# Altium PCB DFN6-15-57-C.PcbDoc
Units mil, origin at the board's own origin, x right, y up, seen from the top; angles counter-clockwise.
Board outline 600 x 1500 mil, 4 copper layers (Top Layer, Metal 2, Metal 3, Bottom Layer), stack 61.6 mil thick; 6 components, 4 nets, 39 pads, 257 vias.
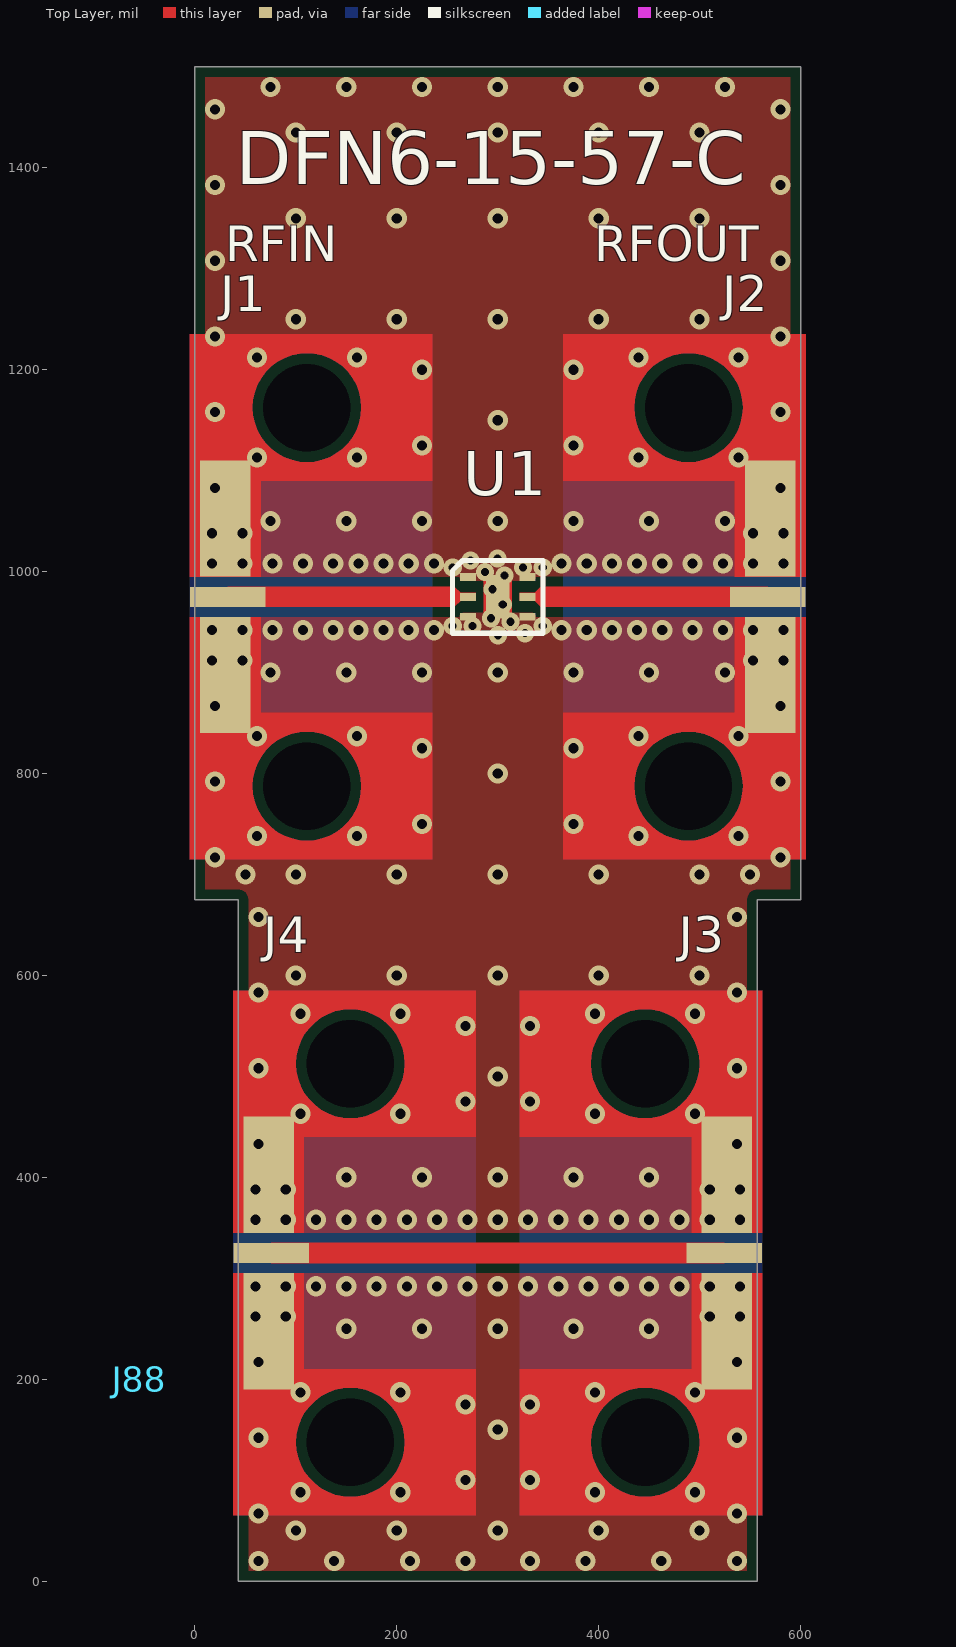
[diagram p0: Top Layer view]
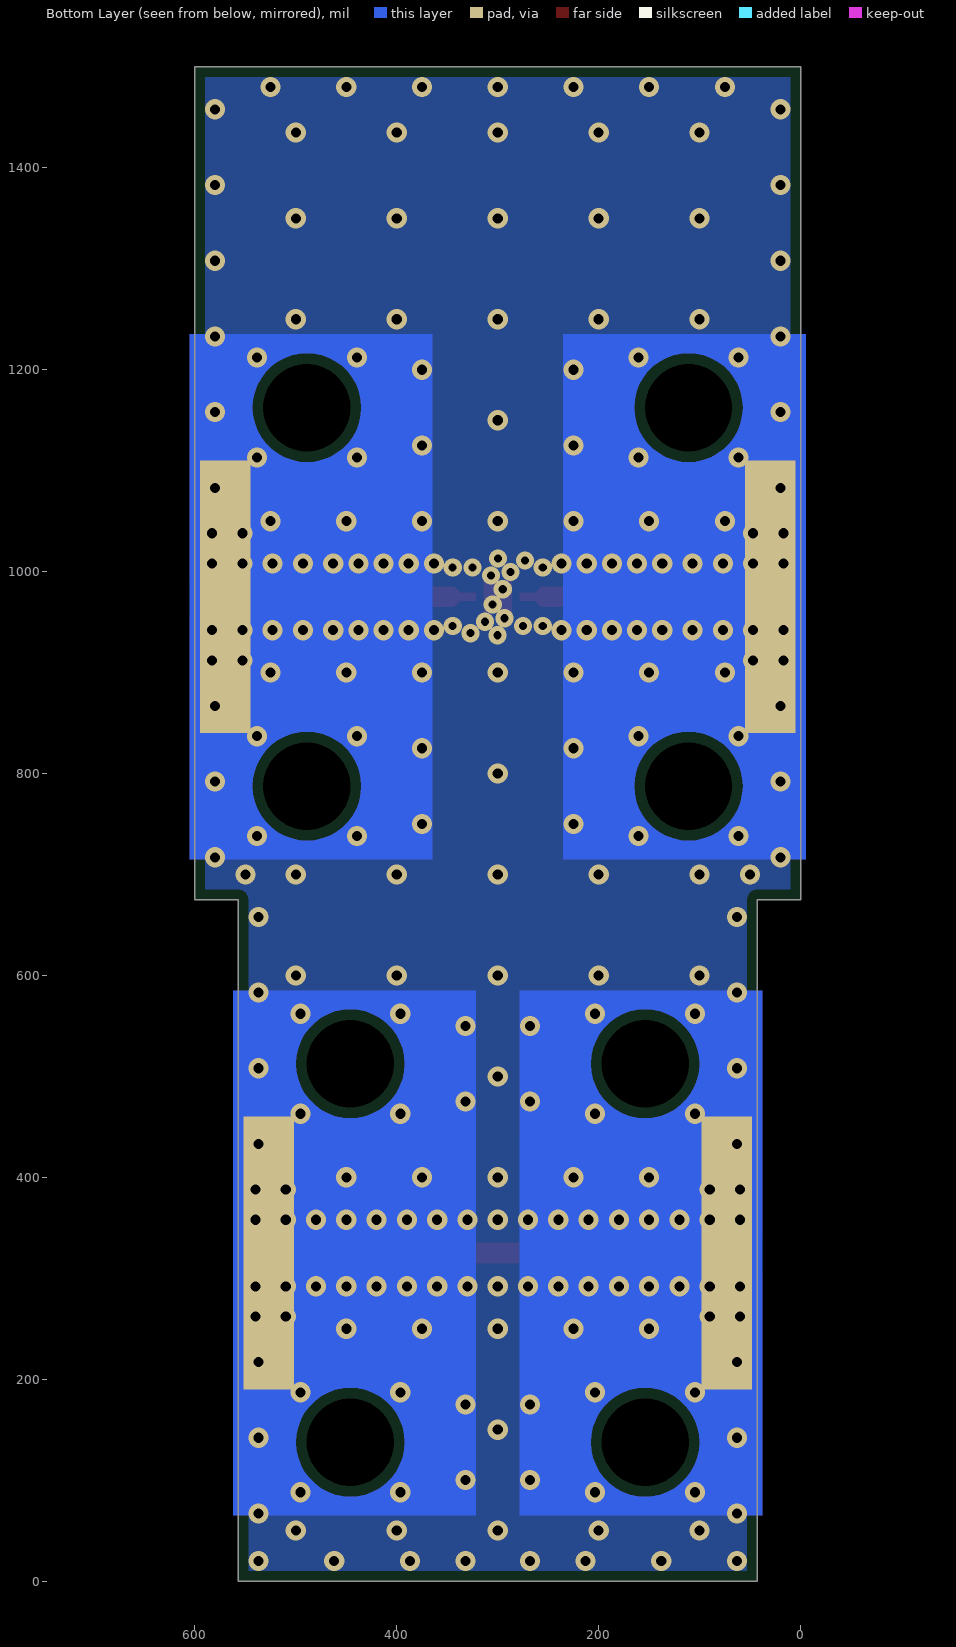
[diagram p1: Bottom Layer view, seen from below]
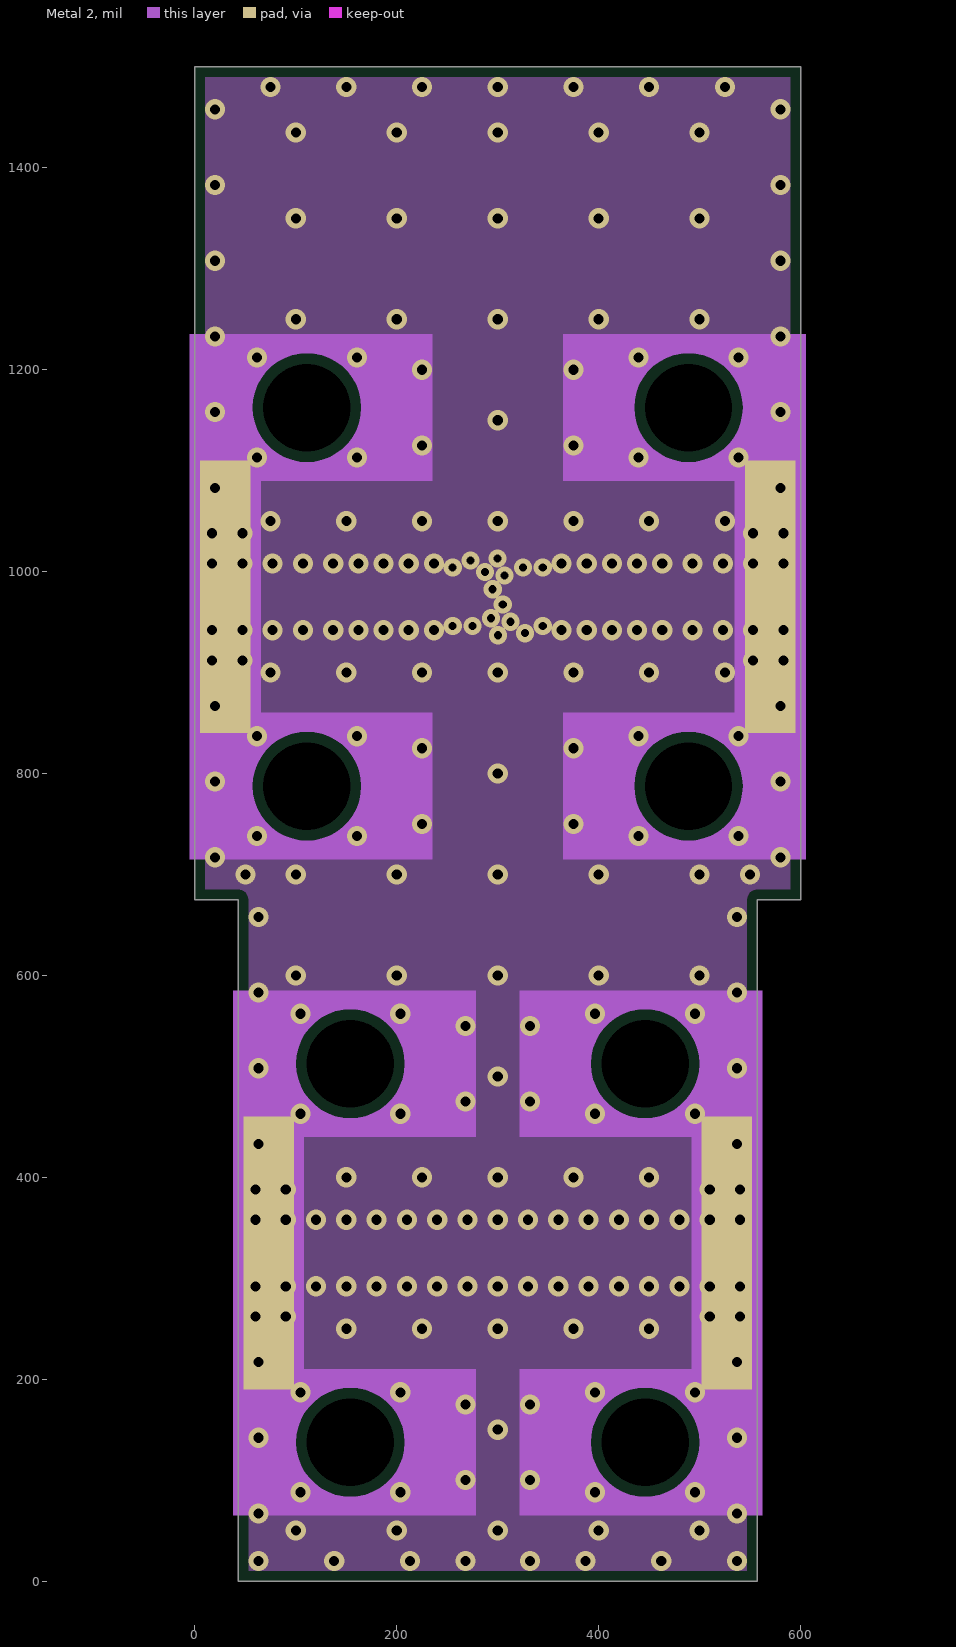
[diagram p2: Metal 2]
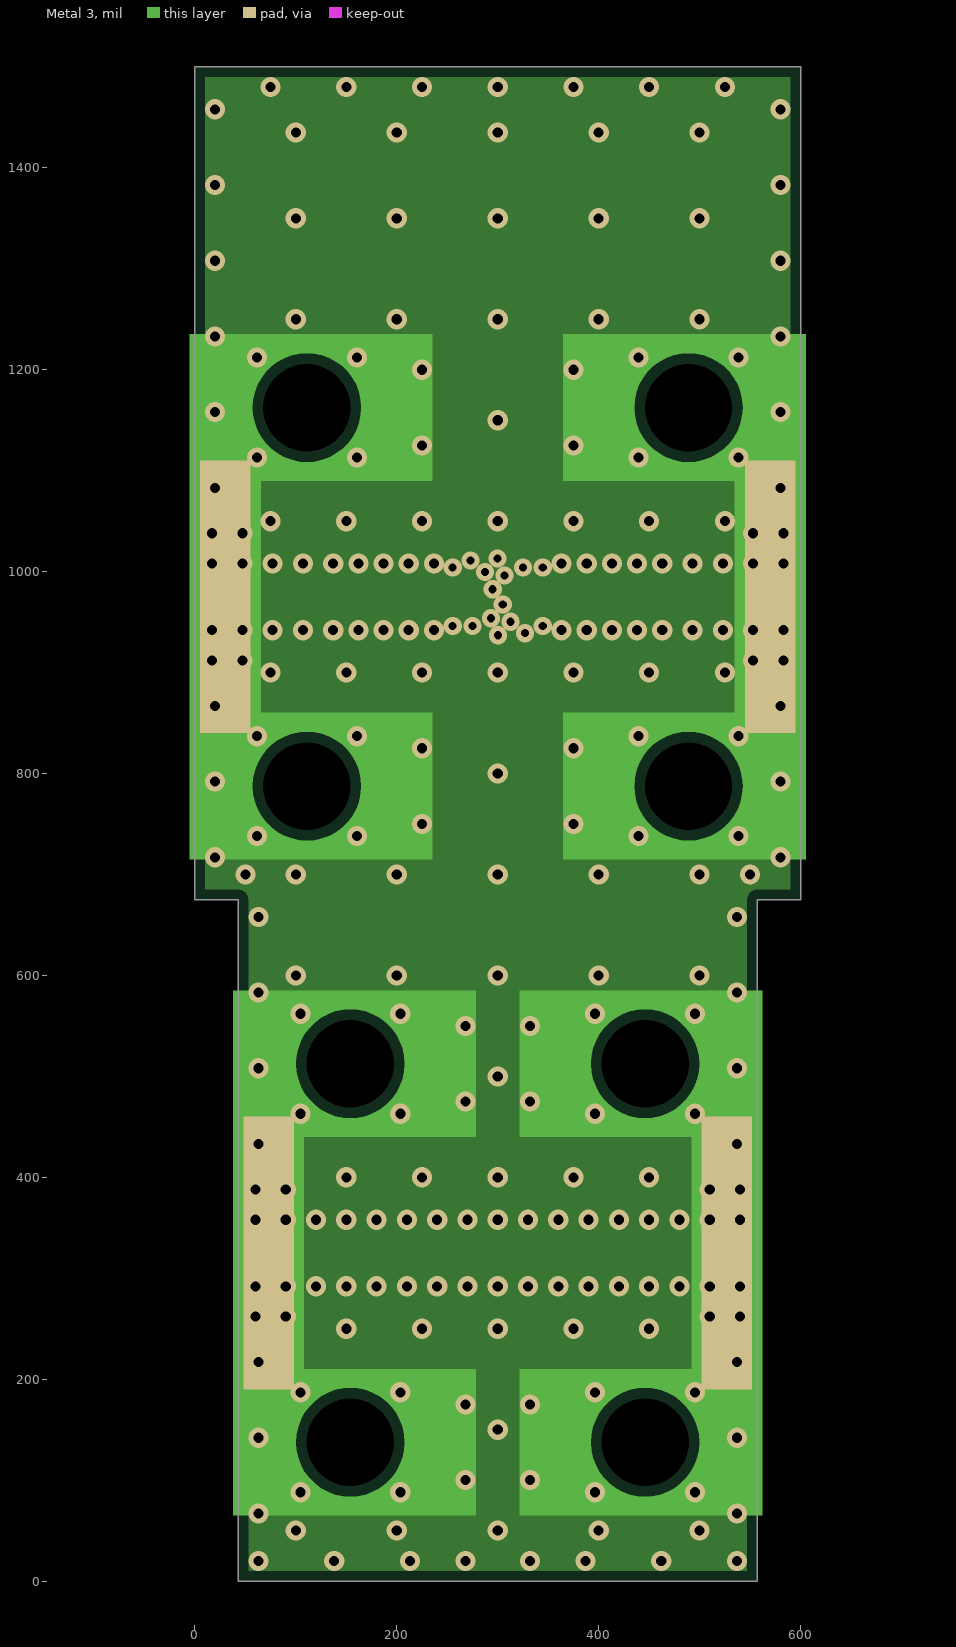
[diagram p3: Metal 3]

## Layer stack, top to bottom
Top Solder: solder mask 0.4, Solder Resist, Dk 4.1
Top Layer: signal copper 1.4
Dielectric 2: core 12, RO4003C, Dk 3.38
Metal 2: signal copper 1.4
Dielectric 1: prepreg 32, FR-4, Dk 4.8
Metal 3: signal copper 1.4
Dielectric 3: core 12, RO4003C, Dk 3.38
Bottom Layer: signal copper 1.4
Bottom Solder: solder mask 0.4, Solder Resist, Dk 4.1

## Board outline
0,675 0,1500 600,1500 600,675 557,675 557,0 43,0 43,675

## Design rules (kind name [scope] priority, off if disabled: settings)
BackDrilling [IsVia and not InNet('GND')] p1: maxstublength=5 usetopbackdrill=TRUE usebottombackdrill=TRUE holeoversize=10 holetolplus=0.2 holetolminus=0.2
BoardOutlineClearance BoardOutlineClearance_Solder_Mask [OnLayer('Top Solder') Or OnLayer('Bottom Solder')] p1: gap=0 ignorepadtopadclearanceinfootprint=FALSE
BoardOutlineClearance [All] p2: gap=10 ignorepadtopadclearanceinfootprint=FALSE
Clearance Clearance_I/O [InNetClass('I/O') vs InNet('GND')] p1: gap=7 ignorepadtopadclearanceinfootprint=TRUE
Clearance Clearance_RF_Strip [InNetClass('RF_Strip') vs InNet('GND')] p2: gap=40 ignorepadtopadclearanceinfootprint=TRUE
Clearance Clearance_RF_15-15-8 [InNetClass('RF_15-15-8') vs InNet('GND')] p3: gap=15 ignorepadtopadclearanceinfootprint=TRUE
Clearance Clearance_RF_20-10-12 [InNetClass('RF_20-10-12') vs InNet('GND')] p4: gap=10 ignorepadtopadclearanceinfootprint=TRUE
Clearance Clearance_RF_30-20-16 [InNetClass('RF_30-20-16') vs InNet('GND')] p5: gap=20 ignorepadtopadclearanceinfootprint=TRUE
Clearance Clearance_RF_28-21-16_FR4 [InNetClass('RF_28-21-16_FR4') vs InNet('GND')] p6: gap=21 ignorepadtopadclearanceinfootprint=TRUE
Clearance Clearance_RF_15-27p5-8 [InNetClass('RF_15-27p5-8') vs InNet('GND')] p7: gap=27.5 ignorepadtopadclearanceinfootprint=TRUE
Clearance Clearance_RF_25-22-40_75ohm [InNetClass('RF_25-22-40_75ohm') vs InNet('GND')] p8: gap=22 ignorepadtopadclearanceinfootprint=TRUE
Clearance Clearance_GND [InNet('GND')] p9: gap=10 ignorepadtopadclearanceinfootprint=TRUE
Clearance [All] p10: gap=6 ignorepadtopadclearanceinfootprint=TRUE
ComponentClearance ComponentClearance_Heatsink [InComponent('All') And OnLayer('Top Layer') vs HasFootprint('Heatsink_wFid')] p1: gap=0 collisioncheckmode=3 verticalgap=0 showdistances=FALSE
ComponentClearance ComponentClearance_PCB_Frame [InComponent('All') And OnLayer('Top Layer') vs HasFootprint('PCB_Frame')] p2: gap=0 collisioncheckmode=3 verticalgap=0 showdistances=FALSE
ComponentClearance [All] p3: gap=10 collisioncheckmode=3 verticalgap=10 showdistances=TRUE
HoleSize [All] p1: absolutevalues=TRUE maxlimit=200 minlimit=8 maxpercent=80.000 minpercent=20.000
MinimumSolderMaskSliver [All] p1: minsoldermaskwidth=5
PlaneClearance [Not InNet('GND')] p1: clearance=20
PlaneConnect [InNet('GND')] p1: planeconnectstyle=Direct reliefexpansion=20 reliefentries=4 reliefconductorwidth=10 reliefairgap=10
PolygonConnect [All vs InNet('GND')] p1: connectstyle=Direct reliefconductorwidth=10 reliefentries=4 polygonreliefangle="90 Angle" airgapwidth=10
RoutingVias [All] p1: holewidth=10 width=20 viastyle="Through Hole" minholewidth=8 minwidth=18 maxholewidth=23.62 maxwidth=33.62
SilkToSilkClearance [All] p1: silktosilkclearance=5
SilkToSolderMaskClearance [IsPad] p1: minsilkscreentomaskgap=5 clearancetoexposedcopper=TRUE
SolderMaskExpansion [All] p1: expansion=1 istentingtop=FALSE
UnRoutedNet [All] p1: checkbadconnections=TRUE
Width [All] p1: maxlimit=100 minlimit=6 preferedwidth=10
22 further rules are at their usual default settings.

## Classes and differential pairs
component class DFN6-15-57-C: J1 J2 J3 J4 U1
net class RF_20-10-12: NetJ1_1 NetJ2_1

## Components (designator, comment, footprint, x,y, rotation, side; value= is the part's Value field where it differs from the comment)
J1 "Clamp_27G_Southwest_RevC" Clamp_27G_Southwest_RevC 0,975 r0 top
J2 "Clamp_27G_Southwest_RevC" Clamp_27G_Southwest_RevC 600,975 r180 top (schematic designator J3)
J3 "Clamp_27G_Southwest_RevC" Clamp_27G_Southwest_RevC 557,325 r180 top (schematic designator J4)
J4 "Clamp_27G_Southwest_RevC" Clamp_27G_Southwest_RevC 43,325 r0 top (schematic designator J5)
J88 "Comment" PCB_Fab_20T-10G-12D_4003 -55,200 r0 top locked
U1 "DFN6_1.5x1.5mm_RevG" DFN6_1.5x1.5mm_RevG 300,975 r0 top

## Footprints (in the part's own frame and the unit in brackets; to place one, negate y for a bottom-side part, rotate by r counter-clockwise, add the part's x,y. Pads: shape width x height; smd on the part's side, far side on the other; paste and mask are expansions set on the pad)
Clamp_27G_Southwest_RevC [mil] "292-04A-6  for CPWG"
  rect 75x20 smd paste-30: 1(32.5,0)
  rect 50x115 smd paste-30 mask-300: 2(30,-77.5) 2(30,77.5)
  rect 50x270 on Mid1: 2(30,0)
  rect 50x270 smd far side: 2(30,0)
  rect 50x270 on Mid2: 2(30,0)
  round 0 hole 86.61 unplated: 3(111,-187.5) 3(111,187.5)
  Top Layer region: -5,20 -5,260 235,260 235,187.5 165,187.5 160.89,208.16 149.18,225.68 131.66,237.39 111,241.5 111,241.5 90.34,237.39 72.82,225.68 61.11,208.16 57,187.5 57,187.5 61.11,166.84 72.82,149.32 90.34,137.61 111,133.5 111,133.5 131.66,137.61 149.18,149.32 160.89,166.84 165,187.5 165,187.5 235,187.5 235,115 65,115 65,20
  Top Layer region: -5,-20 -5,-260 235,-260 235,-187.5 165,-187.5 160.89,-208.16 149.18,-225.68 131.66,-237.39 111,-241.5 111,-241.5 90.34,-237.39 72.82,-225.68 61.11,-208.16 57,-187.5 57,-187.5 61.11,-166.84 72.82,-149.32 90.34,-137.61 111,-133.5 111,-133.5 131.66,-137.61 149.18,-149.32 160.89,-166.84 165,-187.5 165,-187.5 235,-187.5 235,-115 65,-115 65,-20
  Top Layer pour cut-out: 57,187.5 61.11,208.16 72.82,225.68 90.34,237.39 111,241.5 111,241.5 131.66,237.39 149.18,225.68 160.89,208.16 165,187.5 165,187.5 160.89,166.84 149.18,149.32 131.66,137.61 111,133.5 111,133.5 90.34,137.61 72.82,149.32 61.11,166.84 57,187.5
  Top Layer pour cut-out: 57,-187.5 61.11,-166.84 72.82,-149.32 90.34,-137.61 111,-133.5 111,-133.5 131.66,-137.61 149.18,-149.32 160.89,-166.84 165,-187.5 165,-187.5 160.89,-208.16 149.18,-225.68 131.66,-237.39 111,-241.5 111,-241.5 90.34,-237.39 72.82,-225.68 61.11,-208.16 57,-187.5
  Metal 2 region: -5,260 235,260 235,187.5 165,187.5 160.89,208.16 149.18,225.68 131.66,237.39 111,241.5 111,241.5 90.34,237.39 72.82,225.68 61.11,208.16 57,187.5 57,187.5 61.11,166.84 72.82,149.32 90.34,137.61 111,133.5 111,133.5 131.66,137.61 149.18,149.32 160.89,166.84 165,187.5 165,187.5 235,187.5 235,115 65,115 65,-115 235,-115 235,-187.5 165,-187.5 160.89,-166.84 149.18,-149.32 131.66,-137.61 111,-133.5 111,-133.5 90.34,-137.61 72.82,-149.32 61.11,-166.84 57,-187.5 57,-187.5 61.11,-208.16 72.82,-225.68 90.34,-237.39 111,-241.5 111,-241.5 131.66,-237.39 149.18,-225.68 160.89,-208.16 165,-187.5 165,-187.5 235,-187.5 235,-260 -5,-260
  Metal 2 pour cut-out: 57,187.5 61.11,208.16 72.82,225.68 90.34,237.39 111,241.5 111,241.5 131.66,237.39 149.18,225.68 160.89,208.16 165,187.5 165,187.5 160.89,166.84 149.18,149.32 131.66,137.61 111,133.5 111,133.5 90.34,137.61 72.82,149.32 61.11,166.84 57,187.5
  Metal 2 pour cut-out: 57,-187.5 61.11,-166.84 72.82,-149.32 90.34,-137.61 111,-133.5 111,-133.5 131.66,-137.61 149.18,-149.32 160.89,-166.84 165,-187.5 165,-187.5 160.89,-208.16 149.18,-225.68 131.66,-237.39 111,-241.5 111,-241.5 90.34,-237.39 72.82,-225.68 61.11,-208.16 57,-187.5
  Metal 3 region: -5,260 235,260 235,187.5 165,187.5 160.89,208.16 149.18,225.68 131.66,237.39 111,241.5 111,241.5 90.34,237.39 72.82,225.68 61.11,208.16 57,187.5 57,187.5 61.11,166.84 72.82,149.32 90.34,137.61 111,133.5 111,133.5 131.66,137.61 149.18,149.32 160.89,166.84 165,187.5 165,187.5 235,187.5 235,115 65,115 65,-115 235,-115 235,-187.5 165,-187.5 160.89,-166.84 149.18,-149.32 131.66,-137.61 111,-133.5 111,-133.5 90.34,-137.61 72.82,-149.32 61.11,-166.84 57,-187.5 57,-187.5 61.11,-208.16 72.82,-225.68 90.34,-237.39 111,-241.5 111,-241.5 131.66,-237.39 149.18,-225.68 160.89,-208.16 165,-187.5 165,-187.5 235,-187.5 235,-260 -5,-260
  Metal 3 pour cut-out: 57,187.5 61.11,208.16 72.82,225.68 90.34,237.39 111,241.5 111,241.5 131.66,237.39 149.18,225.68 160.89,208.16 165,187.5 165,187.5 160.89,166.84 149.18,149.32 131.66,137.61 111,133.5 111,133.5 90.34,137.61 72.82,149.32 61.11,166.84 57,187.5
  Metal 3 pour cut-out: 57,-187.5 61.11,-166.84 72.82,-149.32 90.34,-137.61 111,-133.5 111,-133.5 131.66,-137.61 149.18,-149.32 160.89,-166.84 165,-187.5 165,-187.5 160.89,-208.16 149.18,-225.68 131.66,-237.39 111,-241.5 111,-241.5 90.34,-237.39 72.82,-225.68 61.11,-208.16 57,-187.5
  Bottom Layer region: -5,260 235,260 235,187.5 165,187.5 160.89,208.16 149.18,225.68 131.66,237.39 111,241.5 111,241.5 90.34,237.39 72.82,225.68 61.11,208.16 57,187.5 57,187.5 61.11,166.84 72.82,149.32 90.34,137.61 111,133.5 111,133.5 131.66,137.61 149.18,149.32 160.89,166.84 165,187.5 165,187.5 235,187.5 235,-187.5 165,-187.5 160.89,-166.84 149.18,-149.32 131.66,-137.61 111,-133.5 111,-133.5 90.34,-137.61 72.82,-149.32 61.11,-166.84 57,-187.5 57,-187.5 61.11,-208.16 72.82,-225.68 90.34,-237.39 111,-241.5 111,-241.5 131.66,-237.39 149.18,-225.68 160.89,-208.16 165,-187.5 165,-187.5 235,-187.5 235,-260 -5,-260
  Bottom Layer pour cut-out: 57,187.5 61.11,208.16 72.82,225.68 90.34,237.39 111,241.5 111,241.5 131.66,237.39 149.18,225.68 160.89,208.16 165,187.5 165,187.5 160.89,166.84 149.18,149.32 131.66,137.61 111,133.5 111,133.5 90.34,137.61 72.82,149.32 61.11,166.84 57,187.5
  Bottom Layer pour cut-out: 57,-187.5 61.11,-166.84 72.82,-149.32 90.34,-137.61 111,-133.5 111,-133.5 131.66,-137.61 149.18,-149.32 160.89,-166.84 165,-187.5 165,-187.5 160.89,-208.16 149.18,-225.68 131.66,-237.39 111,-241.5 111,-241.5 90.34,-237.39 72.82,-225.68 61.11,-208.16 57,-187.5
DFN6_1.5x1.5mm_RevG [mm] "Standard Footprint"
  rect 0.4x0.2 smd paste-100: 1(-0.75,0.5) 2(-0.75,0) 3(-0.75,-0.5) 4(0.75,-0.5) 5(0.75,0) 6(0.75,0.5)
  rect 0.6x1.1 smd paste-100: 7(0,0)
  silkscreen extent -1.14,-0.92 1.14,0.92
PCB_Fab_20T-10G-12D_4003 [mil] "20mil RF 10mil Gap  12mil Dielectric"

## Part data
J1 J2 J3 J4: library part RF_Conn
U1: library part DFN6_1.5x1.5mm, "DFN6 1.5x1.5mm"

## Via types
v1: diameter 20/20/20/20 (per signal layer), hole 10, Top Layer to Bottom Layer, tented both sides, 233 vias
v2: diameter 18/18/18/18 (per signal layer), hole 8, Top Layer to Bottom Layer, tented both sides, 14 vias
v3: diameter 20/20/20/20 (per signal layer), hole 10, Top Layer to Bottom Layer, tented bottom, 8 vias
v4: diameter 18/18/18/18 (per signal layer), hole 8, Top Layer to Bottom Layer, tented bottom, 2 vias

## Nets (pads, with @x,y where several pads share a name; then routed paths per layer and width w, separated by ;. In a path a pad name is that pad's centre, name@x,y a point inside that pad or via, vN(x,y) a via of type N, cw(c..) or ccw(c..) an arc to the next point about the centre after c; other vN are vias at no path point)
GND: J1.2 J2.2 J3.2 J4.2 U1.1 U1.3 U1.4 U1.6 U1.7
  other v1: 63,20 138,20 213,20 268,20 332,20 387,20 462,20 537,20 100,50 200,50 300,50 400,50 500,50 104.5,88 203.5,88 396.5,88 495.5,88 268,100 332,100 63,142 537,142 300,150 268,175 332,175 104.5,187 203.5,187 396.5,187 495.5,187 63,217 537,217 150,250 225,250 300,250 375,250 450,250 60,262 90,262 510,262 540,262 60,292 90,292 120,292 150,292 180,292 210,292 240,292 270,292 300,292 330,292 360,292 390,292 420,292 450,292 480,292 510,292 540,292 60,358 90,358 120,358 150,358 180,358 210,358 240,358 270,358 300,358 330,358 360,358 390,358 420,358 450,358 480,358 510,358 540,358 60,388 90,388 510,388 540,388 150,400 225,400 300,400 375,400 450,400 63,433 537,433 104.5,463 203.5,463 396.5,463 495.5,463 268,475 332,475 300,500 63,508 537,508 268,550 332,550 104.5,562 203.5,562 396.5,562 495.5,562 100,600 200,600 300,600 400,600 500,600 63,658 537,658 50,700 100,700 200,700 300,700 400,700 500,700 550,700 61.5,738 160.5,738 439.5,738 538.5,738 225,750 375,750 20,792 580,792 300,800 225,825 375,825 61.5,837 160.5,837 439.5,837 538.5,837 20,867 580,867 75,900 150,900 225,900 300,900 375,900 450,900 525,900 17,912 47,912 553,912 583,912 17,942 47,942 77,942 107,942 137,942 161.93,942 186.86,942 211.79,942 236.72,942 363.28,942 388.21,942 413.14,942 438.07,942 463,942 493,942 523,942 553,942 583,942 17,1008 47,1008 77,1008 107,1008 137,1008 161.93,1008 186.86,1008 211.79,1008 236.72,1008 363.28,1008 388.21,1008 413.14,1008 438.07,1008 463,1008 493,1008 523,1008 553,1008 583,1008 17,1038 47,1038 553,1038 583,1038 75,1050 150,1050 225,1050 300,1050 375,1050 450,1050 525,1050 20,1083 580,1083 61.5,1113 160.5,1113 439.5,1113 538.5,1113 225,1125 375,1125 300,1150 20,1158 580,1158 225,1200 375,1200 61.5,1212 160.5,1212 439.5,1212 538.5,1212 100,1250 200,1250 300,1250 400,1250 500,1250 20,1308 580,1308 100,1350 200,1350 300,1350 400,1350 500,1350 20,1383 580,1383 100,1435 200,1435 300,1435 400,1435 500,1435 20,1458 580,1458 75,1480 150,1480 225,1480 300,1480 375,1480 450,1480 525,1480
  other v2: 300.2,937.01 327,939 255.37,946 275,946 344.63,946 312.65,950.36 305,967.43 295,982.57 287.35,999.64 255.37,1004 325,1004 344.63,1004 273,1011 299.8,1012.99
  other v3: 63,67 537,67 63,583 537,583 20,717 580,717 20,1233 580,1233
  other v4: 293.23,953.8 306.77,996.2
NetJ1_1: J1.1 U1.2
NetJ2_1: J2.1 U1.5
NetJ3_1: J3.1 J4.1
pads on no net: J1.3 J2.3 J3.3 J4.3

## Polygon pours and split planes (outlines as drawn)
GND on Top Layer "GND_L01_P000" (solid, pour order 0): 0,0 600,0 600,1500 0,1500
GND on Bottom Layer "GND_L04_P001" (solid, pour order 1): 0,0 600,0 600,1500 0,1500
GND on Metal 2 "NONET_L-01_P-001" (solid, pour order 2): 0,0 600,0 600,1500 0,1500
GND on Metal 3 "NONET_L-01_P-001" (solid, pour order 3): 0,0 600,0 600,1500 0,1500

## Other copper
Top Layer:
  rectangle net GND: 38,345 58,360
  rectangle net GND: 38,290 58,305
  rectangle net GND: -5,940 15,955
  rectangle net GND: -5,995 15,1010
  region net GND: 562,305 542,305 542,290 562,290
  region net GND: 562,360 542,360 542,345 562,345
  region net GND: 605,955 585,955 585,940 605,940
  region net GND: 605,1010 585,1010 585,995 605,995
  pour cut-out: 286,990.75 262.6,990.75 262.6,995 255,995 255,955 262.6,955 262.6,959.25 286,959.25
  pour cut-out: 314,990.75 337.4,990.75 337.4,995 345,995 345,955 337.4,955 337.4,959.25 314,959.25
  region net GND: 314,990.75 286,990.75 286,959.25 314,959.25
  region net NetJ1_1: 278.35,978.94 263.22,978.94 257.15,985 32.5,985 32.5,965 257.15,965 263.22,971.06 278.35,971.06
  region net NetJ2_1: 321.65,978.94 336.78,978.94 342.85,985 567.5,985 567.5,965 342.85,965 336.78,971.06 321.65,971.06
  region net NetJ3_1: 75.5,315 75.5,335 524.5,335 524.5,315

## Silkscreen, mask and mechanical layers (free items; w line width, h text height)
Top Overlay:
  text "DFN6-15-57-C" at 40.6,1366.18 h90
  text "RFIN" at 30,1295.8 h60
  text "RFOUT" at 395.51,1295.8 h60
Top Solder:
  region: 300,364 300,286 43,286 43,364
  region: 300,364 300,286 557,286 557,364
  region: 353,1014 353,936 600,936 600,1014
  region: 247,1014 247,936 0,936 0,1014
Bottom Solder:
  region: 0,1500 0,675 43,675 43,0 557,0 557,675 600,675 600,1500
Board_Dimension:
  the board outline again, w10
Drill Drawing:
  lines w15: -1272.5,-2592.5 3752.13,-2592.5 ; -1272.5,-2142.5 3752.13,-2142.5 ; -721.62,-2742.5 -721.62,-1992.5 ; -121.78,-2742.5 -121.78,-1992.5 ; 967.9,-2742.5 967.9,-1992.5 ; 1473.78,-2742.5 1473.78,-1992.5 ; 2207.58,-2742.5 2207.58,-1992.5 ; -1272.5,-2742.5 3752.13,-2742.5 3752.13,-1992.5 -1272.5,-1992.5 -1272.5,-2742.5
  text "Symbol" at -1182.5,-2097.5 h72
  text "Count" at -676.62,-2097.5 h72
  text "Hole Size" at -76.78,-2097.5 h72
  text "Plated" at 1012.9,-2097.5 h72
  text "Hole Type" at 1518.78,-2097.5 h72
  text "Drill Layer Pair" at 2252.58,-2097.5 h72
  text "16" at -676.62,-2247.5 h60
  text "8.00mil (0.203mm)" at -76.78,-2247.5 h60
  text "PTH" at 1012.9,-2247.5 h60
  text "Round" at 1518.78,-2247.5 h60
  text "Top Layer - Bottom Layer" at 2252.58,-2247.5 h60
  text "A" at -1211.59,-2257.49 h66.67
  text "241" at -676.62,-2397.5 h60
  text "10.00mil (0.254mm)" at -76.78,-2397.5 h60
  text "PTH" at 1012.9,-2397.5 h60
  text "Round" at 1518.78,-2397.5 h60
  text "Top Layer - Bottom Layer" at 2252.58,-2397.5 h60
  text "B" at -1211.59,-2407.49 h66.67
  text "8" at -676.62,-2547.5 h60
  text "86.61mil (2.200mm)" at -76.78,-2547.5 h60
  text "NPTH" at 1012.9,-2547.5 h60
  text "Round" at 1518.78,-2547.5 h60
  text "Top Layer - Bottom Layer" at 2252.58,-2547.5 h60
  text "M" at -1211.59,-2557.49 h66.67
  text "265 Total" at -676.62,-2697.5 h60
Document:
  lines w10: -75.99,1092.38 -463,1609.87 -44,384.28 ; -25,711.37 -75,711.37 -75,1246.37 -25,1246.37 ; 6,40 -44,40 -44,575 6,575 ; 150,975 775,1800 225,325 ; 400,975 772.41,1793.06 ; 475,650 980,775 ; 594,40 644,40 644,575 594,575 ; 625,711.37 675,711.37 675,1246.37 625,1246.37 ; 644,384.28 975,350 ; 675.99,1092.38 1063,1609.87 ; 125,590 475,590 475,710 125,710 125,590
  text "Note C" at 1010,736.39 h125
Reference:
  lines w10: 0,675 0,0 43,0 ; 300,292 300,358 ; 300,325 325,325

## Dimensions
0,675 to 600,675 on Mechanical 16
0,1500 to 43,0 on Mechanical 16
